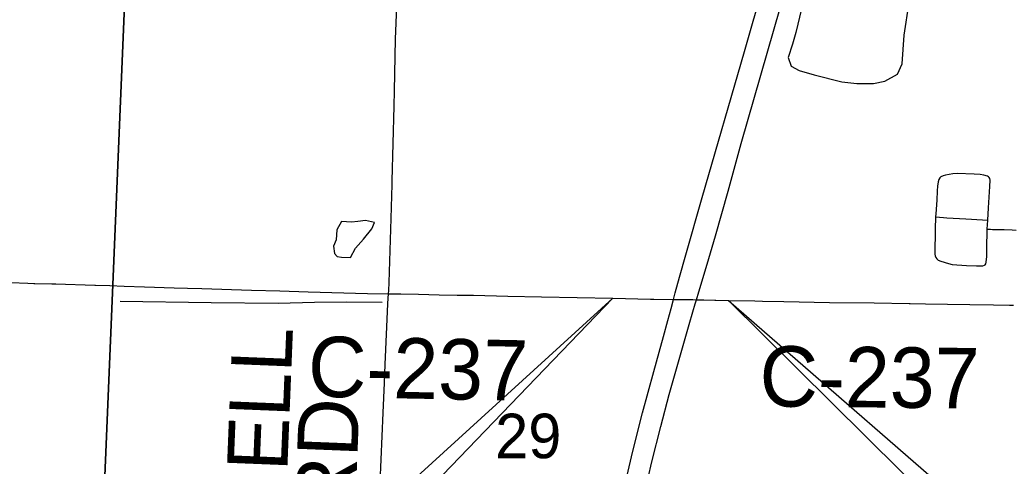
# Model space of a CAD drawing. Extents: x -59 to 43, y 0 to 22.
# Drawn here: x 26.169 to 27.1, y 16.594 to 17.014 of the extents above; entities that cross this region are included whole.
import ezdxf

# ---------------------------------------------------------------- set-up
doc = ezdxf.new("R2010")
doc.units = 0
for name, color, linetype in [('BR_P_Gen_Text', 7, 'Continuous'), ('GM_X_City_Street', 7, 'Continuous'), ('GM_X_County_Road', 7, 'Continuous'), ('GM_X_County_Road_Text', 7, 'Continuous'), ('GM_X_Interstate_Route', 7, 'Continuous'), ('GM_X_Minor_Lake', 7, 'Continuous'), ('GM_X_Minor_River', 7, 'Continuous'), ('GM_X_Section', 7, 'Continuous'), ('GM_X_Section_Text', 7, 'Continuous'), ('SH_Text', 7, 'Continuous')]:
    doc.layers.add(name, color=color, linetype=linetype)

msp = doc.modelspace()

# ---------------------------------------------------------------- linework, layer by layer
at = {"layer": 'BR_P_Gen_Text'}
for points in [[(26.72732, 16.7521), (23.55853, 13.86636), (23.94817, 13.86636)], [(26.8361, 16.75006), (30.15258, 13.86636), (29.75005, 13.86636)]]:
    msp.add_lwpolyline(points, close=True, dxfattribs=at)
at = {"layer": 'GM_X_City_Street'}
for points in [[(27.08016, 16.8255), (27.08079, 16.83715), (27.08214, 16.857), (27.08231, 16.86313), (27.08201, 16.86462), (27.08152, 16.86549), (27.08082, 16.8662), (27.07994, 16.86672), (27.07653, 16.86769), (27.07297, 16.86834), (27.06746, 16.86873), (27.05137, 16.8693), (27.04715, 16.86889), (27.04049, 16.86764), (27.03818, 16.86706), (27.03613, 16.86609), (27.03498, 16.86508), (27.03415, 16.86368), (27.03342, 16.8615), (27.03272, 16.85732), (27.03254, 16.85306), (27.03219, 16.84431), (27.03117, 16.8313), (27.03108, 16.82857)], [(27.03108, 16.82857), (27.03069, 16.81703), (27.03027, 16.79348), (27.03054, 16.79188), (27.03119, 16.79035), (27.03215, 16.789), (27.03335, 16.78798), (27.03602, 16.78676), (27.04305, 16.78459), (27.04658, 16.78389), (27.06015, 16.78278), (27.06942, 16.78263), (27.07553, 16.78262), (27.07701, 16.78299), (27.07774, 16.78353), (27.07829, 16.78431), (27.07872, 16.78582), (27.07923, 16.7913), (27.0794, 16.79872), (27.07959, 16.81662)], [(27.03108, 16.82857), (27.03864, 16.82784), (27.04172, 16.82754), (27.05964, 16.82663), (27.0751, 16.82578), (27.08016, 16.8255)], [(27.07959, 16.81662), (27.07976, 16.82164), (27.08012, 16.82475), (27.08016, 16.8255)], [(27.1067, 16.81575), (27.10323, 16.81589), (27.09567, 16.81621), (27.0863, 16.81637), (27.08446, 16.8165), (27.08259, 16.81654), (27.07959, 16.81662)]]:
    msp.add_lwpolyline(points, dxfattribs=at)
at = {"layer": 'GM_X_County_Road'}
for points in [[(26.52195, 16.94691), (26.52304, 16.99572), (26.5242, 17.02625), (26.52512, 17.04248), (26.52586, 17.04872)], [(26.51631, 16.75621), (26.51654, 16.75928), (26.51689, 16.76671), (26.51822, 16.80708), (26.51893, 16.82694), (26.51971, 16.85896), (26.51977, 16.86112), (26.5198, 16.86236), (26.52171, 16.93256), (26.52195, 16.94691)], [(26.04251, 16.77009), (26.05959, 16.76957), (26.07759, 16.76926), (26.12041, 16.768), (26.14464, 16.76755), (26.17691, 16.76626), (26.18278, 16.76603)], [(26.18278, 16.76603), (26.18376, 16.76599), (26.19952, 16.76562), (26.20353, 16.76548), (26.24, 16.76429), (26.24064, 16.76427), (26.25436, 16.76388), (26.26766, 16.76337)], [(26.26766, 16.76337), (26.28675, 16.76287), (26.3147, 16.76186), (26.32727, 16.76151)], [(26.32727, 16.76151), (26.3408, 16.76115), (26.3874, 16.75971), (26.41412, 16.75887), (26.44083, 16.75806), (26.49675, 16.75653), (26.51631, 16.75621)], [(26.49713, 16.25783), (26.49722, 16.2627), (26.49821, 16.31589), (26.50018, 16.36806), (26.50087, 16.38793), (26.50132, 16.40223), (26.50193, 16.4165), (26.50283, 16.44446), (26.5051, 16.49911), (26.50636, 16.53141), (26.50738, 16.55252), (26.50846, 16.5786), (26.51134, 16.64442), (26.51258, 16.67236), (26.51331, 16.68974), (26.51471, 16.72514), (26.51577, 16.74683), (26.51601, 16.75209), (26.51631, 16.75621)], [(26.51631, 16.75621), (26.52783, 16.75603), (26.54462, 16.75572), (26.56388, 16.75529), (26.58105, 16.75504)], [(26.58105, 16.75504), (26.59621, 16.75482), (26.62852, 16.75389), (26.66021, 16.75345), (26.72732, 16.7521), (26.76297, 16.7512)], [(26.76297, 16.7512), (26.76585, 16.75113), (26.78447, 16.75094), (26.80252, 16.75075), (26.80603, 16.75068), (26.82329, 16.75032)], [(26.82329, 16.75032), (26.82433, 16.7503), (26.8361, 16.75006), (26.86096, 16.74948), (26.86825, 16.74934), (26.88829, 16.74893), (26.93117, 16.74815), (26.97321, 16.74762), (27.00614, 16.74723)], [(27.00614, 16.74723), (27.00714, 16.74722), (27.02162, 16.74686), (27.04212, 16.74638), (27.06325, 16.74623), (27.08563, 16.7459), (27.10055, 16.74564), (27.10423, 16.74558)]]:
    msp.add_lwpolyline(points, dxfattribs=at)
at = {"layer": 'GM_X_Interstate_Route'}
for points in [[(26.80488, 16.7469), (26.80603, 16.75068), (26.80832, 16.75821), (26.81613, 16.78392), (26.82413, 16.8107), (26.83584, 16.85261), (26.84824, 16.89756), (26.88522, 17.02601), (26.90421, 17.09172), (26.92694, 17.17102), (26.95053, 17.25414), (26.95079, 17.2551)], [(26.73829, 16.57488), (26.74608, 16.60815), (26.75528, 16.64429), (26.76596, 16.68325), (26.77101, 16.70123), (26.77518, 16.71619), (26.77913, 16.73096), (26.78215, 16.74226), (26.78447, 16.75094), (26.78614, 16.7572), (26.7901, 16.772), (26.79615, 16.79291), (26.81148, 16.84674), (26.8513, 16.98408), (26.90551, 17.17359)], [(26.70376, 16.29996), (26.70789, 16.32113), (26.72128, 16.38819), (26.73232, 16.44621), (26.74762, 16.52241), (26.75724, 16.56805), (26.76418, 16.59837), (26.77245, 16.63156), (26.78052, 16.6616), (26.79923, 16.72738), (26.80258, 16.73934), (26.80488, 16.7469)]]:
    msp.add_lwpolyline(points, dxfattribs=at)
at = {"layer": 'GM_X_Minor_Lake'}
msp.add_line((26.48756, 16.82403), (26.48149, 16.82367), dxfattribs=at)
for points in [[(26.90487, 17.02422), (26.89953, 17.0019), (26.89629, 16.99095), (26.89226, 16.97848), (26.89515, 16.97007), (26.90268, 16.96614), (26.91667, 16.96209), (26.94278, 16.95554), (26.95681, 16.95377), (26.97277, 16.95387), (26.98345, 16.95596), (26.99535, 16.96258), (26.9997, 16.97238), (27.00133, 16.99932), (27.00606, 17.03001)], [(26.48149, 16.82367), (26.47201, 16.82408), (26.46781, 16.81649), (26.46702, 16.807), (26.46473, 16.80092), (26.46547, 16.79408), (26.46812, 16.79142), (26.47229, 16.79065), (26.48063, 16.79024), (26.48521, 16.79896), (26.49283, 16.80768), (26.50082, 16.81715), (26.50312, 16.82323), (26.49478, 16.82515), (26.48756, 16.82403)]]:
    msp.add_lwpolyline(points, dxfattribs=at)
at = {"layer": 'GM_X_Minor_River'}
msp.add_lwpolyline([(26.51048, 16.74798), (26.47671, 16.74846), (26.44674, 16.74817), (26.41258, 16.74713), (26.3496, 16.74769), (26.26385, 16.74908)], dxfattribs=at)
at = {"layer": 'GM_X_Section'}
for points in [[(25.18784, 17.29346), (26.27822, 17.27501), (26.23614, 16.26224), (25.17438, 16.29397), (25.17305, 16.308)], [(27.27299, 17.25298), (27.23736, 16.24538), (26.23614, 16.26224), (26.27822, 17.27501)]]:
    msp.add_lwpolyline(points, close=True, dxfattribs=at)
at = {"layer": 'SH_Text'}
for p, q in [((26.72732, 16.7521), (26.76297, 16.7512)), ((26.76297, 16.7512), (26.76585, 16.75113)), ((26.76585, 16.75113), (26.78447, 16.75094)), ((26.78447, 16.75094), (26.80252, 16.75075)), ((26.80252, 16.75075), (26.82329, 16.75032)), ((26.82329, 16.75032), (26.8361, 16.75006))]:
    msp.add_line(p, q, dxfattribs=at)

# ---------------------------------------------------------------- texts
at = {"layer": 'GM_X_County_Road_Text'}
for s, rotation, p in [('CAMPBELL', 87.68845, (26.41019, 16.31887)), ('C-237', 358.89841, (26.4402, 16.65958)), ('C-237', 359.44776, (26.86527, 16.65039)), ('HILL RD', 87.7323, (26.47767, 16.36575))]:
    msp.add_text(s, height=0.056818, rotation=rotation, dxfattribs=at).set_placement(p)
at = {"layer": 'GM_X_Section_Text'}
msp.add_text('29', height=0.041856, rotation=0.00001, dxfattribs=at).set_placement((26.61672, 16.60166))

doc.saveas('drawing.dxf')
